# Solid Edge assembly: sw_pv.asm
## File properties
Author: Sham
Template: Sync Iso Assembly.asm
Last saved by: TIET
Revision: 5
Application: Solid Edge
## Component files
base.par
Screw.par
moveable jaw.par
handle.par
handle screw.par
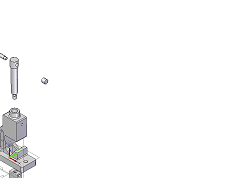
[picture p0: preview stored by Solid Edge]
